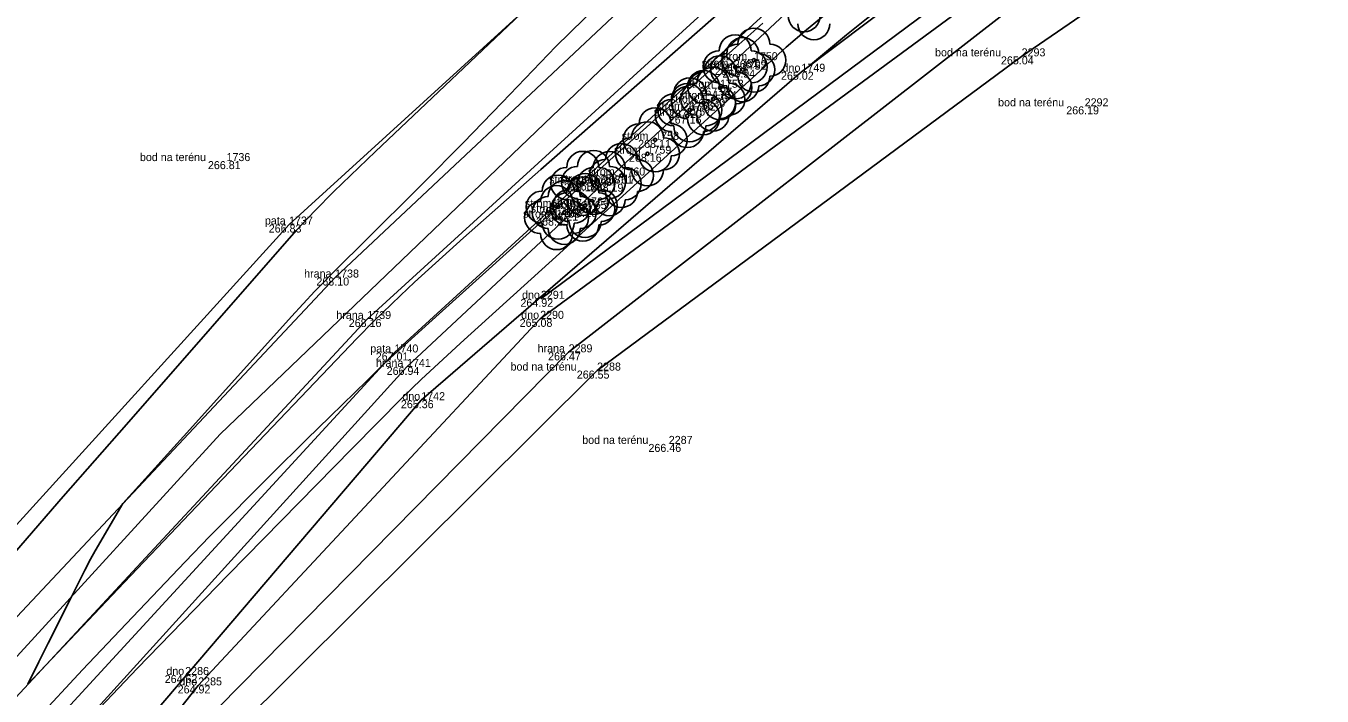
# Model space of a CAD drawing. Extents: x -567962 to -566460, y -1093720 to -1089838.
# Drawn here: x -566913.4 to -566832.4, y -1090226.7 to -1090184.9 of the extents above; entities that cross this region are included whole.
import ezdxf

# ---------------------------------------------------------------- set-up
doc = ezdxf.new("R2010")
doc.units = 0
for name, color, linetype in [('0_osa hráze', 7, 'Continuous'), ('bod_znacka', 7, 'Continuous'), ('cislo_bodu', 7, 'Continuous'), ('Doměření - kraj pole', 7, 'Continuous'), ('hlavni_vrst', 7, 'Continuous'), ('hrana_L', 7, 'Continuous'), ('hrana_P', 7, 'Continuous'), ('kod_bodu', 7, 'Continuous'), ('norm_vrst', 7, 'Continuous'), ('stromy', 7, 'Continuous'), ('vyska_bodu', 7, 'Continuous')]:
    doc.layers.add(name, color=color, linetype=linetype)

msp = doc.modelspace()

# ---------------------------------------------------------------- linework, layer by layer
at = {"layer": '0_osa hráze'}
msp.add_lwpolyline([(-566876.582, -1090186.718), (-566901.274, -1090210.335), (-566914.414, -1090224.7)], dxfattribs=at)
msp.add_arc((-566738.34, -1090331.249), 200, 128.63535, 133.7258, dxfattribs=at)
at = {"layer": 'bod_znacka'}
for p, q in [((-566867.92, -1090186.99), (-566867.92, -1090186.99)), ((-566851.19, -1090186.75), (-566851.19, -1090186.75)), ((-566869.09, -1090187.41), (-566869.09, -1090187.41)), ((-566868.62, -1090187.58), (-566868.62, -1090187.58)), ((-566864.95, -1090187.71), (-566864.95, -1090187.71)), ((-566870.04, -1090188.71), (-566870.04, -1090188.71)), ((-566871.07, -1090189.64), (-566871.07, -1090189.64)), ((-566870.48, -1090189.42), (-566870.48, -1090189.42)), ((-566872.08, -1090190.45), (-566872.08, -1090190.45)), ((-566871.93, -1090190.09), (-566871.93, -1090190.09)), ((-566847.25, -1090189.87), (-566847.25, -1090189.87)), ((-566874.09, -1090191.96), (-566874.09, -1090191.96)), ((-566874.57, -1090192.83), (-566874.57, -1090192.83)), ((-566900.88, -1090193.29), (-566900.88, -1090193.29)), ((-566876.2, -1090194.19), (-566876.2, -1090194.19)), ((-566878.62, -1090194.68), (-566878.62, -1090194.68)), ((-566877.94, -1090194.62), (-566877.94, -1090194.62)), ((-566876.96, -1090194.7), (-566876.96, -1090194.7)), ((-566880.15, -1090196.16), (-566880.15, -1090196.16)), ((-566878.47, -1090196.06), (-566878.47, -1090196.06)), ((-566880.25, -1090196.82), (-566880.25, -1090196.82)), ((-566879.77, -1090196.5), (-566879.77, -1090196.5)), ((-566878.61, -1090196.28), (-566878.61, -1090196.28)), ((-566896.97, -1090197.25), (-566896.97, -1090197.25)), ((-566894.09, -1090200.56), (-566894.09, -1090200.56)), ((-566881.23, -1090201.89), (-566881.23, -1090201.89)), ((-566892.08, -1090203.15), (-566892.08, -1090203.15)), ((-566881.28, -1090203.14), (-566881.28, -1090203.14)), ((-566890.38, -1090205.24), (-566890.38, -1090205.24)), ((-566879.5, -1090205.23), (-566879.5, -1090205.23)), ((-566889.6, -1090206.14), (-566889.6, -1090206.14)), ((-566877.72, -1090206.37), (-566877.72, -1090206.37)), ((-566888.71, -1090208.22), (-566888.71, -1090208.22)), ((-566873.24, -1090210.95), (-566873.24, -1090210.95)), ((-566903.46, -1090225.38), (-566903.46, -1090225.38)), ((-566902.65, -1090226.03), (-566902.65, -1090226.03))]:
    msp.add_line(p, q, dxfattribs=at)
at = {"layer": 'Doměření - kraj pole'}
msp.add_lwpolyline([(-567047.906, -1090663.012), (-567047.627, -1090662.294), (-567014.86, -1090563.09), (-567002.362, -1090535.532), (-566955.49, -1090317.15), (-566941.63, -1090287.13), (-566940.57, -1090285.53), (-566924.46, -1090259.19), (-566900.35, -1090228.87), (-566877.72, -1090206.37), (-566851.19, -1090186.75), (-566766.44, -1090128.68), (-566717.21, -1090096.34), (-566711.98, -1090092.48)], dxfattribs=at)
at = {"layer": 'hlavni_vrst'}
msp.add_lwpolyline([(-566864.386, -1090187.286), (-566862.132, -1090185.411), (-566860.89, -1090184.412), (-566859.25, -1090183.114), (-566857.836, -1090182.013), (-566856.185, -1090180.753), (-566854.566, -1090179.53), (-566852.907, -1090178.3), (-566851.041, -1090176.931), (-566849.375, -1090175.725), (-566845.549, -1090173.001), (-566843.141, -1090171.318)], dxfattribs=at)
at = {"layer": 'hrana_L'}
for p, q in [((-566896.97, -1090197.25), (-566873.54, -1090175.93)), ((-566870.94, -1090178.83), (-566894.09, -1090200.56)), ((-566868.38, -1090181.54), (-566892.08, -1090203.15)), ((-566866.53, -1090183.45), (-566890.38, -1090205.24)), ((-566889.6, -1090206.14), (-566865.98, -1090184.11)), ((-566920.16, -1090222.76), (-566896.97, -1090197.25)), ((-566894.09, -1090200.56), (-566917.27, -1090225.23)), ((-566892.08, -1090203.15), (-566914.61, -1090227.38)), ((-566890.38, -1090205.24), (-566912.62, -1090229.4)), ((-566911.56, -1090230.31), (-566889.6, -1090206.14))]:
    msp.add_line(p, q, dxfattribs=at)
for points in [[(-567053.87, -1090661.84), (-567020.06, -1090563.34), (-567005.258, -1090534.966), (-566958.763, -1090315.674), (-566944.67, -1090284.66), (-566926.49, -1090256.26), (-566902.65, -1090226.03), (-566881.28, -1090203.14), (-566853.44, -1090182.668), (-566715.257, -1090089.634)], [(-567050.54, -1090661.95), (-567017.83, -1090562.99), (-567002.61, -1090535.52), (-566957.72, -1090316.45), (-566942.31, -1090285.07), (-566925.11, -1090257.71), (-566901.37, -1090227.4), (-566879.5, -1090205.23), (-566852.16, -1090184), (-566767.57, -1090126.99), (-566713.28, -1090090.76)], [(-566881.23, -1090201.89), (-566854.215, -1090181.819), (-566730.44, -1090098.63)]]:
    msp.add_lwpolyline(points, dxfattribs=at)
at = {"layer": 'hrana_P'}
for p, q in [((-566864.95, -1090187.71), (-566838.46, -1090167.8)), ((-566888.71, -1090208.22), (-566864.95, -1090187.71)), ((-566910.59, -1090233.83), (-566888.71, -1090208.22))]:
    msp.add_line(p, q, dxfattribs=at)
at = {"layer": 'norm_vrst'}
for points in [[(-566909.945, -1090228.646), (-566906.461, -1090224.978), (-566900.779, -1090219.13), (-566893.019, -1090211.23), (-566889.884, -1090208.055), (-566888.724, -1090206.923), (-566886.247, -1090204.653), (-566880.063, -1090199.051), (-566870.54, -1090190.395), (-566865.91, -1090186.173), (-566864.63, -1090185.085), (-566863, -1090183.753), (-566861.763, -1090182.757), (-566858.775, -1090180.398), (-566855.672, -1090177.999), (-566852.179, -1090175.418), (-566839.061, -1090166.004), (-566837.956, -1090165.259), (-566836.061, -1090164.037), (-566833.079, -1090162.132), (-566828.853, -1090159.464)], [(-566877.625, -1090183.53), (-566880.295, -1090186.129), (-566883.643, -1090189.63), (-566886.085, -1090192.144), (-566888.601, -1090194.683), (-566892.385, -1090198.429), (-566893.803, -1090199.822), (-566895.355, -1090201.421), (-566896.815, -1090202.986), (-566903.164, -1090210.057), (-566907.353, -1090214.676), (-566909.097, -1090217.628), (-566909.383, -1090218.151), (-566909.732, -1090218.829), (-566910.564, -1090220.5), (-566912.034, -1090223.396), (-566912.614, -1090224.563), (-566913.292, -1090225.963), (-566907.282, -1090219.603), (-566901.116, -1090213.129), (-566892.715, -1090204.353), (-566891.703, -1090203.31), (-566890.007, -1090201.68), (-566889.124, -1090200.845), (-566886.062, -1090198.078), (-566881.227, -1090193.804), (-566869.069, -1090183.107)], [(-566881.707, -1090183.361), (-566891.565, -1090192.685), (-566894.17, -1090195.183), (-566895.367, -1090196.403), (-566896.532, -1090197.628), (-566907.137, -1090209.746), (-566911.08, -1090214.232), (-566916.13, -1090220.032)], [(-566912.766, -1090228.176), (-566909.871, -1090225.056), (-566906.762, -1090221.768), (-566903.457, -1090218.318), (-566901.934, -1090216.742), (-566898.074, -1090212.843), (-566895.887, -1090210.668), (-566894.409, -1090209.248), (-566892.094, -1090206.995), (-566890.927, -1090205.834), (-566890.625, -1090205.57), (-566887.592, -1090202.823), (-566873.597, -1090190.24), (-566868.872, -1090186.014), (-566867.359, -1090184.679)]]:
    msp.add_lwpolyline(points, dxfattribs=at)
at = {"layer": 'stromy'}
for centre in [(-566867.92, -1090186.99), (-566869.09, -1090187.41), (-566868.62, -1090187.58), (-566870.04, -1090188.71), (-566871.07, -1090189.64), (-566870.48, -1090189.42), (-566872.08, -1090190.45), (-566871.93, -1090190.09), (-566874.09, -1090191.96), (-566874.57, -1090192.83), (-566878.62, -1090194.68), (-566877.94, -1090194.62), (-566876.2, -1090194.19), (-566876.96, -1090194.7), (-566880.15, -1090196.16), (-566878.61, -1090196.28), (-566878.47, -1090196.06), (-566880.25, -1090196.82), (-566879.77, -1090196.5)]:
    msp.add_circle(centre, 0.1, dxfattribs=at)
for centre, start, end in [((-566864.78, -1090184.21), 180, 0), ((-566864.17, -1090184.71), 180, 0), ((-566869.09, -1090186.41), 0, 180), ((-566868.62, -1090186.58), 0, 180), ((-566867.92, -1090185.99), 0, 180), ((-566870.09, -1090187.41), 90, 270), ((-566868.92, -1090186.99), 90, 270), ((-566868.09, -1090187.41), 270, 90), ((-566866.92, -1090186.99), 270, 90), ((-566870.04, -1090187.71), 0, 180), ((-566869.62, -1090187.58), 90, 270), ((-566867.62, -1090187.58), 270, 90), ((-566871.93, -1090189.09), 0, 180), ((-566871.07, -1090188.64), 0, 180), ((-566871.04, -1090188.71), 90, 270), ((-566870.48, -1090188.42), 0, 180), ((-566869.04, -1090188.71), 270, 90), ((-566867.92, -1090187.99), 180, 0), ((-566872.08, -1090189.45), 0, 180), ((-566872.07, -1090189.64), 90, 270), ((-566871.48, -1090189.42), 90, 270), ((-566869.09, -1090188.41), 180, 0), ((-566870.07, -1090189.64), 270, 90), ((-566868.62, -1090188.58), 180, 0), ((-566869.48, -1090189.42), 270, 90), ((-566873.08, -1090190.45), 90, 270), ((-566872.93, -1090190.09), 90, 270), ((-566871.08, -1090190.45), 270, 90), ((-566870.04, -1090189.71), 180, 0), ((-566870.93, -1090190.09), 270, 90), ((-566874.09, -1090190.96), 0, 180), ((-566870.48, -1090190.42), 180, 0), ((-566875.09, -1090191.96), 90, 270), ((-566874.57, -1090191.83), 0, 180), ((-566873.09, -1090191.96), 270, 90), ((-566871.93, -1090191.09), 180, 0), ((-566871.07, -1090190.64), 180, 0), ((-566875.57, -1090192.83), 90, 270), ((-566873.57, -1090192.83), 270, 90), ((-566872.08, -1090191.45), 180, 0), ((-566878.62, -1090193.68), 0, 180), ((-566877.94, -1090193.62), 0, 180), ((-566876.96, -1090193.7), 0, 180), ((-566876.2, -1090193.19), 0, 180), ((-566874.09, -1090192.96), 180, 0), ((-566879.62, -1090194.68), 90, 270), ((-566878.94, -1090194.62), 90, 270), ((-566877.96, -1090194.7), 90, 270), ((-566877.2, -1090194.19), 90, 270), ((-566877.62, -1090194.68), 270, 90), ((-566876.94, -1090194.62), 270, 90), ((-566875.96, -1090194.7), 270, 90), ((-566875.2, -1090194.19), 270, 90), ((-566880.15, -1090195.16), 0, 180), ((-566879.77, -1090195.5), 0, 180), ((-566878.61, -1090195.28), 0, 180), ((-566878.47, -1090195.06), 0, 180), ((-566874.57, -1090193.83), 180, 0), ((-566881.15, -1090196.16), 90, 270), ((-566880.25, -1090195.82), 0, 180), ((-566879.61, -1090196.28), 90, 270), ((-566879.47, -1090196.06), 90, 270), ((-566879.15, -1090196.16), 270, 90), ((-566877.61, -1090196.28), 270, 90), ((-566877.47, -1090196.06), 270, 90), ((-566876.2, -1090195.19), 180, 0), ((-566881.25, -1090196.82), 90, 270), ((-566880.77, -1090196.5), 90, 270), ((-566878.62, -1090195.68), 180, 0), ((-566879.25, -1090196.82), 270, 90), ((-566877.94, -1090195.62), 180, 0), ((-566878.77, -1090196.5), 270, 90), ((-566876.96, -1090195.7), 180, 0), ((-566880.25, -1090197.82), 180, 0), ((-566880.15, -1090197.16), 180, 0), ((-566879.77, -1090197.5), 180, 0), ((-566878.61, -1090197.28), 180, 0), ((-566878.47, -1090197.06), 180, 0)]:
    msp.add_arc(centre, 1, start, end, dxfattribs=at)

# ---------------------------------------------------------------- texts
at = {"layer": 'cislo_bodu'}
for s, p in [('1750', (-566867.92, -1090186.99)), ('2293', (-566851.19, -1090186.75)), ('1751', (-566869.09, -1090187.41)), ('1752', (-566868.62, -1090187.58)), ('1749', (-566864.95, -1090187.71)), ('1754', (-566870.48, -1090189.42)), ('1753', (-566870.04, -1090188.71)), ('1756', (-566871.93, -1090190.09)), ('1755', (-566871.07, -1090189.64)), ('2292', (-566847.25, -1090189.87)), ('1757', (-566872.08, -1090190.45)), ('1758', (-566874.09, -1090191.96)), ('1736', (-566900.88, -1090193.29)), ('1759', (-566874.57, -1090192.83)), ('1760', (-566876.2, -1090194.19)), ('1763', (-566878.62, -1090194.68)), ('1762', (-566877.94, -1090194.62)), ('1761', (-566876.96, -1090194.7)), ('1767', (-566880.15, -1090196.16)), ('1766', (-566879.77, -1090196.5)), ('1765', (-566878.61, -1090196.28)), ('1764', (-566878.47, -1090196.06)), ('1737', (-566896.97, -1090197.25)), ('1768', (-566880.25, -1090196.82)), ('1738', (-566894.09, -1090200.56)), ('2291', (-566881.23, -1090201.89)), ('1739', (-566892.08, -1090203.15)), ('2290', (-566881.28, -1090203.14)), ('1740', (-566890.38, -1090205.24)), ('2289', (-566879.5, -1090205.23)), ('1741', (-566889.6, -1090206.14)), ('2288', (-566877.72, -1090206.37)), ('1742', (-566888.71, -1090208.22)), ('2287', (-566873.24, -1090210.95)), ('2286', (-566903.46, -1090225.38)), ('2285', (-566902.65, -1090226.03))]:
    msp.add_text(s, height=0.5, dxfattribs=at).set_placement(p)
at = {"layer": 'kod_bodu'}
for s, p in [('bod na terénu', (-566856.599, -1090186.75)), ('strom', (-566871.184, -1090187.41)), ('strom', (-566870.714, -1090187.58)), ('strom', (-566870.014, -1090186.99)), ('dno', (-566866.131, -1090187.71)), ('strom', (-566872.134, -1090188.71)), ('strom', (-566874.024, -1090190.09)), ('strom', (-566873.164, -1090189.64)), ('strom', (-566872.574, -1090189.42)), ('bod na terénu', (-566852.659, -1090189.87)), ('strom', (-566874.174, -1090190.45)), ('strom', (-566876.184, -1090191.96)), ('bod na terénu', (-566906.289, -1090193.29)), ('strom', (-566876.664, -1090192.83)), ('strom', (-566878.294, -1090194.19)), ('strom', (-566880.714, -1090194.68)), ('strom', (-566880.034, -1090194.62)), ('strom', (-566879.054, -1090194.7)), ('strom', (-566882.244, -1090196.16)), ('strom', (-566881.864, -1090196.5)), ('strom', (-566880.704, -1090196.28)), ('strom', (-566880.564, -1090196.06)), ('pata', (-566898.482, -1090197.25)), ('strom', (-566882.344, -1090196.82)), ('hrana', (-566896.027, -1090200.56)), ('dno', (-566882.411, -1090201.89)), ('hrana', (-566894.017, -1090203.15)), ('dno', (-566882.461, -1090203.14)), ('pata', (-566891.892, -1090205.24)), ('hrana', (-566881.437, -1090205.23)), ('hrana', (-566891.537, -1090206.14)), ('bod na terénu', (-566883.129, -1090206.37)), ('dno', (-566889.891, -1090208.22)), ('bod na terénu', (-566878.649, -1090210.95)), ('dno', (-566904.641, -1090225.38)), ('dno', (-566903.831, -1090226.03))]:
    msp.add_text(s, height=0.5, dxfattribs=at).set_placement(p)
at = {"layer": 'vyska_bodu'}
for s, p in [('266.09', (-566869.176, -1090187.49)), ('265.04', (-566852.481, -1090187.25)), ('266.94', (-566870.36, -1090187.91)), ('266.94', (-566869.89, -1090188.08)), ('265.02', (-566866.229, -1090188.21)), ('267.37', (-566871.325, -1090189.21)), ('267.32', (-566872.353, -1090190.14)), ('267.30', (-566871.761, -1090189.92)), ('267.16', (-566873.243, -1090190.95)), ('267.20', (-566873.211, -1090190.59)), ('266.19', (-566848.4, -1090190.37)), ('268.11', (-566875.155, -1090192.46)), ('268.16', (-566875.731, -1090193.33)), ('266.81', (-566902.041, -1090193.79)), ('268.17', (-566877.375, -1090194.69)), ('268.18', (-566879.793, -1090195.18)), ('268.17', (-566879.115, -1090195.12)), ('268.19', (-566878.121, -1090195.2)), ('268.21', (-566881.323, -1090196.66)), ('268.16', (-566879.631, -1090196.56)), ('268.23', (-566881.531, -1090197.32)), ('268.21', (-566880.943, -1090197)), ('268.16', (-566879.771, -1090196.78)), ('266.83', (-566898.24, -1090197.75)), ('268.10', (-566895.261, -1090201.06)), ('264.92', (-566882.511, -1090202.39)), ('268.16', (-566893.241, -1090203.65)), ('265.08', (-566882.559, -1090203.64)), ('267.01', (-566891.553, -1090205.74)), ('266.47', (-566880.783, -1090205.73)), ('266.94', (-566890.87, -1090206.64)), ('266.55', (-566878.99, -1090206.87)), ('265.36', (-566889.98, -1090208.72)), ('266.46', (-566874.51, -1090211.45)), ('264.62', (-566904.741, -1090225.88)), ('264.92', (-566903.931, -1090226.53))]:
    msp.add_text(s, height=0.5, dxfattribs=at).set_placement(p)

doc.saveas('drawing.dxf')
